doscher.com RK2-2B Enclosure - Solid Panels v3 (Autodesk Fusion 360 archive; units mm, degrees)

design "Recovery Kit v2 and v2b Frame - Solid Panels" references "6886K111_Flush-Mount 16 mm Panel-Mount Push-Button Switch", "1422N13_Panel-Mount Data Adapter", "6168T59_Push-In Signal Power Connectors(1)"
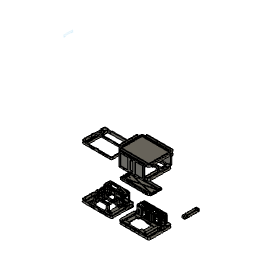
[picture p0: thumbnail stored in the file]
parameter "d2034" = 15
parameter "d2035" = 2.8
parameter "d1378" = 9.5
parameter "d1379" = 10
parameter "d1380" = 9.5
parameter "d1381" = 10
parameter "d1382" = 9.5
parameter "d1383" = 10
parameter "d1384" = 9.5
parameter "d1385" = 10
parameter "d1386" = 2.8
parameter "d1387" = 2.8
parameter "d1388" = 2.8
parameter "d1389" = 2.8
parameter "d1390" = 2.8
parameter "d1391" = 2.8
parameter "d1392" = -2000
parameter "d1393" = 0
parameter "d1394" = -3.5
parameter "d1395" = 6
parameter "d1396" = -3.5
parameter "d1397" = 6
parameter "d1398" = -3.5
parameter "d1399" = 6
parameter "d1400" = -3.5
parameter "d1401" = 6
parameter "d1402" = -3.5
parameter "d1403" = 6
parameter "d1404" = -3.5
parameter "d1405" = 6
parameter "d1406" = -3.5
parameter "d1407" = 6
parameter "d1408" = -3.5
parameter "d1409" = 6
parameter "d1410" = 2.8
parameter "d1411" = 2.8
parameter "d1412" = 2.8
parameter "d1413" = 2.8
parameter "d1414" = -1000
parameter "d1415" = 0
parameter "d1416" = 2.8
parameter "d1417" = 2.8
parameter "d1418" = -1000
parameter "d1419" = 0
parameter "d1420" = -3.5
parameter "d1421" = 6
parameter "d1422" = -3.5
parameter "d1423" = 6
parameter "d1424" = -3.5
parameter "d1425" = 6
parameter "d1426" = -3.5
parameter "d1427" = 6
parameter "d1428" = -3.5
parameter "d1429" = 6
parameter "d1430" = -3.5
parameter "d1431" = 6
parameter "d1432" = 8
parameter "d1433" = 4
parameter "d1434" = 8
parameter "d1435" = 10
parameter "d1436" = -3.5
parameter "d1437" = 0
parameter "d1438" = 8
parameter "d1439" = 8
parameter "d1440" = 8
parameter "d1441" = 8
parameter "d1442" = 10
parameter "d1443" = -3.5
parameter "d1444" = 0
parameter "d1446" = 2
parameter "d1447" = -5
parameter "d1448" = 0
parameter "d1450" = 2
parameter "d1451" = 5
parameter "d1452" = -5
parameter "d1453" = -10
parameter "d1454" = 0
parameter "d1455" = -5
parameter "d1456" = 0
parameter "d1458" = 2
parameter "d1460" = 2
parameter "d1462" = 2
parameter "d1463" = 5
parameter "d1464" = -5
parameter "d1465" = -10
parameter "d1466" = 0
parameter "d1468" = 2
parameter "d1469" = -5
parameter "d1470" = 0
parameter "d1472" = 2
parameter "d1473" = 10
parameter "d1474" = 12
parameter "d1475" = 10
parameter "d1476" = 12
parameter "d1477" = 10
parameter "d1478" = 12
parameter "d1479" = 10
parameter "d1480" = 12
parameter "d1481" = 2.8
parameter "d1482" = 2.8
parameter "d1483" = 2.8
parameter "d1484" = 2.8
parameter "d1485" = -100
parameter "d1486" = 0
parameter "d1487" = -2
parameter "d1488" = 0
parameter "d1489" = 3
parameter "d1490" = 2.8
parameter "d1491" = 2.8
parameter "d1492" = 2.8
parameter "d1493" = 2.8
parameter "d1494" = -40
parameter "d1495" = 0
parameter "d1496" = -410
parameter "d1497" = 0
parameter "d1498" = -3.5
parameter "d1499" = 6
parameter "d1502" = 6
parameter "d1503" = 6
parameter "d1504" = 6
parameter "d1505" = 6
parameter "d1506" = 6
parameter "d1507" = 8
parameter "d1508" = 8
parameter "d1509" = 8
parameter "d1510" = 8
parameter "d1511" = 8
parameter "d1512" = 8
parameter "d1513" = 8
parameter "d1514" = 8
parameter "d1515" = 8
parameter "d1516" = 8
parameter "d1517" = 8
parameter "d1518" = 8
parameter "d1519" = 8
parameter "d1520" = 8
parameter "d1521" = 8
parameter "d1522" = 8
parameter "d1523" = 8
parameter "d1524" = 8
parameter "d1525" = 8
parameter "d1526" = 8
parameter "d1527" = -3.5
parameter "d1528" = 0
parameter "d1529" = 0.4
parameter "d1530" = -15
parameter "d1531" = 0
parameter "d1532" = -10
parameter "d1533" = 10
parameter "d1534" = 20
parameter "d1535" = 10
parameter "d1536" = 20
parameter "d1537" = -15
parameter "d1538" = 0
parameter "d1539" = 10
parameter "d1540" = 15
parameter "d1541" = 10
parameter "d1542" = 15
parameter "d1543" = 2.8
parameter "d1544" = 2.8
parameter "d1545" = -20
parameter "d1546" = 0
parameter "d1547" = 10
parameter "d1548" = 15
parameter "d1549" = 10
parameter "d1550" = 15
parameter "d1551" = 2.8
parameter "d1552" = 2.8
parameter "d1553" = -20
parameter "d1554" = 0
parameter "d1555" = 3
parameter "d1556" = 30
parameter "d1557" = 0
parameter "d1558" = -30
parameter "d1559" = 0
parameter "d1560" = 30
parameter "d1561" = 0
parameter "d1562" = -30
parameter "d1563" = 0
parameter "d1565" = 3
parameter "d1566" = 3
parameter "d1567" = 5
parameter "d1568" = 0
parameter "d1569" = -2
parameter "d1570" = 2.8
parameter "d1571" = -2
parameter "d1572" = 2.8
parameter "d1573" = -3
parameter "d1574" = 6
parameter "d1575" = -3
parameter "d1576" = 6
parameter "d1577" = -50
parameter "d1578" = 2.8
parameter "d1579" = -50
parameter "d1580" = 2.8
parameter "d1581" = -50
parameter "d1582" = 2.8
parameter "d1583" = -75
parameter "d1584" = 2.8
parameter "d1585" = -70
parameter "d1586" = 2.8
parameter "d1587" = -100
parameter "d1588" = 2.8
parameter "d1589" = -100
parameter "d1590" = 2.8
parameter "d1591" = -100
parameter "d1592" = 2.8
parameter "d1593" = -100
parameter "d1594" = 2.8
parameter "d1595" = -2
parameter "d1596" = 2.8
parameter "d1597" = -2
parameter "d1598" = 2.8
parameter "d1599" = -2
parameter "d1600" = 2.8
parameter "d1601" = -2
parameter "d1602" = 2.8
parameter "d1603" = -2
parameter "d1604" = 2.8
parameter "d1605" = -2
parameter "d1606" = 2.8
parameter "d1607" = -2
parameter "d1608" = 2.8
parameter "d1609" = -2
parameter "d1610" = 2.8
parameter "d1611" = -2
parameter "d1612" = 2.8
parameter "d1613" = -2
parameter "d1614" = 2.8
parameter "d1619" = -20
parameter "d1620" = 2.8
parameter "d1621" = -15
parameter "d1622" = 0
parameter "d1623" = -15
parameter "d1624" = 2.8
parameter "d1625" = -15
parameter "d1626" = 2.8
parameter "d1627" = -15
parameter "d1628" = 2.8
parameter "d1629" = -15
parameter "d1630" = 2.8
parameter "d1631" = -15
parameter "d1632" = 2.8
parameter "d1633" = -15
parameter "d1634" = 2.8
parameter "d1637" = 20
parameter "d1638" = 20
parameter "d1639" = -3.5
parameter "d1640" = 0
parameter "d1641" = -1.5
parameter "d1642" = 0
parameter "d1643" = 10
parameter "d1644" = 0
parameter "d1646" = 2
parameter "d1647" = -35
parameter "d1648" = 0
parameter "d1649" = -40
parameter "d1650" = 0
parameter "d1651" = -5
parameter "d1652" = 0
parameter "d1653" = -35
parameter "d1654" = 0
parameter "d1655" = 5
parameter "d1656" = 0
parameter "d1657" = -35
parameter "d1658" = 0
parameter "d1659" = 5
parameter "d1660" = 0
parameter "d1661" = -250
parameter "d1662" = 0
parameter "d1663" = -2
parameter "d1664" = 0
parameter "d1665" = -2
parameter "d1666" = 0
parameter "d1667" = 10
parameter "d1668" = -10
parameter "d1669" = -10
parameter "d1670" = 0
parameter "d1671" = 5
parameter "d1672" = -5
parameter "d1673" = 0
parameter "d1675" = 3
parameter "d1676" = 5
parameter "d1677" = 0
parameter "d1678" = 20
parameter "d1679" = 20
parameter "d1680" = 100
parameter "d1681" = 100
parameter "d1682" = 10
parameter "d1683" = 10
parameter "d1684" = -5
parameter "d1685" = 0
parameter "d1686" = -0.5
parameter "d1687" = 0
parameter "d1688" = -0.5
parameter "d1689" = 0
parameter "d1690" = -1
parameter "d1691" = 2.8
parameter "d1692" = -1
parameter "d1693" = 2.8
parameter "d1694" = -1
parameter "d1695" = 2.8
parameter "d1696" = -1
parameter "d1697" = 2.8
parameter "d1698" = -1
parameter "d1699" = 2.8
parameter "d1700" = -1
parameter "d1701" = 2.8
parameter "d1702" = -1
parameter "d1703" = 2.8
parameter "d1704" = -1
parameter "d1705" = 2.8
parameter "d1706" = 12.5
parameter "d1707" = 12.5
parameter "d1708" = 12.5
parameter "d1709" = 12.5
parameter "d1710" = -10
parameter "d1711" = 0
parameter "d1712" = 10
parameter "d1713" = 10
parameter "d1715" = 3
parameter "d1716" = -0.5
parameter "d1717" = 0
parameter "d1718" = -10
parameter "d1719" = 0
parameter "d1720" = 1
parameter "d1721" = -5
parameter "d1722" = 0
parameter "d1723" = 42
parameter "d1724" = 70
parameter "d1725" = 42
parameter "d1726" = 70
parameter "d1727" = 170
parameter "d1728" = 42
parameter "d1729" = 170
parameter "d1730" = 42
parameter "d1731" = 14
parameter "d1732" = 14
parameter "d1733" = 14
parameter "d1734" = 14
parameter "d1735" = 14
parameter "d1736" = 14
parameter "d1737" = 14
parameter "d1738" = 14
parameter "d1739" = -5
parameter "d1740" = 0
parameter "d1741" = 11
parameter "d1742" = 7
parameter "d1743" = 7
parameter "d1744" = 7
parameter "d1745" = 7
parameter "d1746" = 7
parameter "d1747" = 7
parameter "d1748" = 7
parameter "d1749" = 7
parameter "d1750" = 7
parameter "d1751" = 7
parameter "d1752" = 7
parameter "d1753" = 7
parameter "d1754" = 7
parameter "d1755" = 7
parameter "d1756" = 7
parameter "d1757" = 7
parameter "d1758" = 2.8
parameter "d1759" = 2.8
parameter "d1760" = 2.8
parameter "d1761" = 2.8
parameter "d1762" = 2.8
parameter "d1763" = 2.8
parameter "d1764" = 2.8
parameter "d1765" = 2.8
parameter "d1766" = -70
parameter "d1767" = 0
parameter "d1768" = -320
parameter "d1769" = 0
parameter "d1770" = -7
parameter "d1771" = -12
parameter "d1772" = 5
parameter "d1773" = -5
parameter "d1774" = 5
parameter "d1775" = -5
parameter "d1776" = 7
parameter "d1777" = 0
parameter "d1779" = 2
parameter "d1780" = 5
parameter "d1781" = 5
parameter "d1782" = 5
parameter "d1783" = 5
parameter "d1784" = -10
parameter "d1785" = 0
parameter "d1786" = -5
parameter "d1787" = 0
parameter "d1788" = -4
parameter "d1789" = 0
parameter "d1790" = 2
parameter "d1791" = 0
parameter "d1792" = -3
parameter "d1793" = -3
parameter "d1794" = -3
parameter "d1795" = -3
parameter "d1796" = 3
parameter "d1797" = 0
parameter "d1798" = 6
parameter "d1799" = 6
parameter "d1800" = 6
parameter "d1801" = 6
parameter "d1802" = 6
parameter "d1803" = 6
parameter "d1804" = 6
parameter "d1805" = 6
parameter "d1806" = 6
parameter "d1807" = 6
parameter "d1808" = 6
parameter "d1809" = 6
parameter "d1810" = 6
parameter "d1811" = 6
parameter "d1812" = 6
parameter "d1813" = 6
parameter "d1814" = 6
parameter "d1815" = 6
parameter "d1816" = 6
parameter "d1817" = 6
parameter "d1818" = 6
parameter "d1819" = 6
parameter "d1820" = 6
parameter "d1821" = 6
parameter "d1822" = -3.5
parameter "d1823" = 0
parameter "d1825" = 3
parameter "d1826" = 7
parameter "d1827" = 20
parameter "d1828" = 7
parameter "d1829" = -10
parameter "d1830" = 0
parameter "d1831" = 2
parameter "d1832" = -2
parameter "d1833" = 0
parameter "d1834" = -10
parameter "d1835" = 0
parameter "d1836" = 4
parameter "d1837" = 4
parameter "d1838" = 4
parameter "d1839" = -10
parameter "d1840" = 0
parameter "d1841" = -4
parameter "d1842" = 0
parameter "d1843" = -4
parameter "d1844" = 0
parameter "d1845" = 3.5
parameter "d1847" = 7
parameter "d1848" = -2
parameter "d1849" = 0
parameter "d1850" = 4
parameter "d1851" = 0
parameter "d1852" = 3.5
parameter "d1853" = -60
parameter "d1854" = 0
parameter "d1855" = 47
parameter "d1856" = 0
parameter "d1857" = -16
parameter "d1858" = 0
parameter "d1859" = 7
parameter "d1861" = 3
parameter "d1862" = 1
parameter "d1863" = 0
parameter "d1864" = -1
parameter "d1865" = 0
parameter "d1866" = -1
parameter "d1867" = 0
parameter "d1868" = -20
parameter "d1869" = 0
parameter "d1870" = -30
parameter "d1871" = 0
parameter "d1872" = -30
parameter "d1873" = 0
parameter "d1875" = 2
parameter "d1878" = 5.25
parameter "d1879" = 4
parameter "d1880" = 4
parameter "d1881" = 0
parameter "d1882" = 12
parameter "d1883" = 12
parameter "d1884" = 12
parameter "d1885" = 12
parameter "d1886" = -5
parameter "d1887" = 0
parameter "d1888" = 5
parameter "d1890" = 2
parameter "d1891" = 12
parameter "d1892" = 12
parameter "d1893" = 12
parameter "d1894" = 12
parameter "d1895" = -5
parameter "d1896" = 0
parameter "d1897" = 5
parameter "d1899" = 2
parameter "d1900" = 8
parameter "d1901" = 0
parameter "d1902" = -0.5
parameter "d1903" = 0
parameter "d1904" = -0.5
parameter "d1905" = 0
parameter "d1906" = 20
parameter "d1907" = 0
parameter "d1908" = 5
parameter "d1909" = -10
parameter "d1910" = 0
parameter "d1912" = 4
parameter "d1914" = -3.5
parameter "d1915" = 6.5
parameter "d1917" = -3.5
parameter "d1918" = 6.5
parameter "d1919" = 3
parameter "d1921" = 2
parameter "d1922" = 3
parameter "d1923" = 3
parameter "d1924" = -3
parameter "d1925" = -20
parameter "d1926" = 0
parameter "d1927" = -20
parameter "d1928" = 0
parameter "d1929" = 5
parameter "d1930" = 15
parameter "d1931" = 5
parameter "d1932" = 15
parameter "d1933" = -20
parameter "d1934" = 0
parameter "d1935" = 14
parameter "d1936" = 0
parameter "d1937" = 5
parameter "d1938" = 0
parameter "d1939" = 5
parameter "d1940" = 0
parameter "d1941" = -4
parameter "d1942" = 0
parameter "d1943" = -0.5
parameter "d1944" = 0
parameter "d1945" = -56
parameter "d1946" = 0
parameter "d1947" = -0.5
parameter "d1948" = 0
parameter "d1949" = 5
parameter "d1950" = 0
parameter "d1951" = 2
parameter "d1952" = 0
parameter "d1953" = 24
parameter "d1954" = 7
parameter "d1955" = 0
parameter "d1957" = 4
parameter "d1958" = 1
parameter "d1959" = 0
parameter "d1960" = -0.3
parameter "d1961" = 0
parameter "d1962" = -30
parameter "d1963" = 0
parameter "d1964" = 6.5
parameter "d1965" = 6.5
parameter "d1966" = 6.5
parameter "d1967" = 21
parameter "d1968" = 6.5
parameter "d1969" = 21
parameter "d1970" = 6.5
parameter "d1971" = 21
parameter "d1972" = 6.5
parameter "d1973" = 21
parameter "d1974" = 6.5
parameter "d1975" = 21
parameter "d1976" = 6.5
parameter "d1977" = 21
parameter "d1978" = 6.5
parameter "d1979" = 21
parameter "d1980" = 6.5
parameter "d1981" = 21
parameter "d1982" = 6.5
parameter "d1983" = -9.5
parameter "d1984" = 0
parameter "d1986" = 2
parameter "d1988" = 2
parameter "d1990" = 2
parameter "d1992" = 2
parameter "d1994" = 2
parameter "d1995" = -3
parameter "d1996" = 3
parameter "d1997" = -3
parameter "d1998" = 0
parameter "d1999" = 3
parameter "d2000" = -10
parameter "d2001" = 0
parameter "d2002" = 3
parameter "d2003" = 0
parameter "d2005" = 3
parameter "d2006" = -14
parameter "d2007" = 0
parameter "d2008" = 1
parameter "d2009" = 0
parameter "d2010" = -1
parameter "d2011" = 0
parameter "d2012" = 2
parameter "d2013" = 0
parameter "d2014" = -2
parameter "d2015" = 0
parameter "d2016" = 2.5
parameter "d2017" = 0
parameter "d2018" = 2
parameter "d2019" = 0
parameter "d2020" = -4.5
parameter "d2021" = 0
parameter "d2022" = -6.5
parameter "d2023" = 0
parameter "d2024" = -6.5
parameter "d2025" = 0
parameter "d2026" = -6.5
parameter "d2027" = 0
parameter "d639" = 5
parameter "d640" = 0
parameter "d641" = 5
parameter "d642" = 5
parameter "d643" = -50
parameter "d644" = 11.1
parameter "d645" = -2
parameter "d646" = 10
parameter "d647" = 0
parameter "d648" = -1.5
parameter "d649" = 0
parameter "d650" = 3
parameter "d651" = -20
parameter "d652" = 5
parameter "d653" = -10
parameter "d654" = 5
parameter "d655" = 29
parameter "d656" = 10
parameter "d657" = -5
parameter "d658" = 0
parameter "d659" = 1
parameter "d660" = 2
parameter "d661" = 3
parameter "d662" = 3
parameter "d663" = 5
parameter "d664" = 0
parameter "d665" = 5
parameter "d666" = 5
parameter "d667" = 0
parameter "d668" = 5
parameter "d669" = 5
parameter "d670" = 0
parameter "d671" = 5
parameter "d672" = 5
parameter "d673" = 0
parameter "d674" = 3
parameter "d675" = 3
parameter "d676" = 3
parameter "d678" = 0.1
parameter "d679" = -60
parameter "d680" = 0
parameter "d681" = 2
parameter "d682" = 1
parameter "d683" = 5
parameter "d684" = 0
parameter "d685" = 5
parameter "d686" = 1
parameter "d687" = -4
parameter "d688" = 2.8
parameter "d689" = -4
parameter "d690" = 2.8
parameter "d691" = -4
parameter "d692" = 2.8
parameter "d693" = -4
parameter "d694" = 2.8
parameter "d695" = 5
parameter "d696" = 0
parameter "d697" = 5
parameter "d698" = 0
parameter "d699" = 5
parameter "d700" = 5
parameter "d701" = -3
parameter "d702" = 2.8
parameter "d703" = -3
parameter "d704" = 2.8
parameter "d705" = -3
parameter "d706" = 2.8
parameter "d707" = -3
parameter "d708" = 2.8
parameter "d709" = -2
parameter "d710" = 0
parameter "d711" = -2
parameter "d712" = 0
parameter "d713" = -2
parameter "d714" = 0
parameter "d715" = -2
parameter "d716" = 0
parameter "d717" = 225
parameter "d718" = 74
parameter "d719" = 36.5
parameter "d720" = 36.5
parameter "d721" = 17.9
parameter "d722" = 17.9
parameter "d723" = 56
parameter "d724" = 56
parameter "d725" = 17.5
parameter "d726" = 17.5
parameter "d727" = 56
parameter "d728" = 56
parameter "d729" = 17.5
parameter "d730" = 17.5
parameter "d731" = 1.8
parameter "d732" = 1.8
parameter "d733" = 1.8
parameter "d734" = 1.8
parameter "d735" = 1.8
parameter "d736" = 1.8
parameter "d737" = -5
parameter "d738" = 7
parameter "d739" = 7
parameter "d740" = 7
parameter "d741" = 7
parameter "d742" = 7
parameter "d743" = 7
parameter "d744" = 5
parameter "d745" = 0
parameter "d746" = -4
parameter "d747" = 3
parameter "d748" = 0
parameter "d749" = 2
parameter "d750" = 7
parameter "d751" = 2
parameter "d752" = 7
parameter "d753" = 2
parameter "d754" = 7
parameter "d755" = 2
parameter "d756" = 7
parameter "d757" = 2
parameter "d758" = 7
parameter "d759" = 2
parameter "d760" = 7
parameter "d761" = -50
parameter "d762" = 1.8
parameter "d763" = -50
parameter "d764" = 1.8
parameter "d765" = -50
parameter "d766" = 1.8
parameter "d767" = -80
parameter "d768" = 1.8
parameter "d769" = -50
parameter "d770" = 1.8
parameter "d771" = -50
parameter "d772" = 1.8
parameter "d773" = 1
parameter "d774" = -3
parameter "d775" = 0
parameter "d776" = 5
parameter "d777" = 0
parameter "d778" = 2
parameter "d779" = 115
parameter "d780" = 20
parameter "d781" = 2
parameter "d782" = 0
parameter "d783" = 10
parameter "d784" = 20
parameter "d785" = 0
parameter "d786" = 10
parameter "d787" = 0
parameter "d788" = -10
parameter "d789" = 0
parameter "d790" = 15
parameter "d791" = -12
parameter "d792" = 0
parameter "d794" = 2
parameter "d796" = 5
parameter "d797" = -5
parameter "d798" = 5
parameter "d799" = -27
parameter "d800" = 0
parameter "d802" = 0.1
parameter "d803" = 110
parameter "d804" = 0
parameter "d805" = 0
parameter "d806" = -1
parameter "d807" = 2
parameter "d808" = 5
parameter "d809" = 0
parameter "d810" = -15
parameter "d811" = 0
parameter "d812" = 3
parameter "d813" = 1
parameter "d814" = -3
parameter "d815" = 0
parameter "d816" = -3
parameter "d817" = -50
parameter "d818" = 0
parameter "d820" = 0.1
parameter "d821" = -0.1
parameter "d822" = -0.1
parameter "d823" = 3
parameter "d824" = -0.5
parameter "d825" = 0
parameter "d826" = -0.5
parameter "d827" = 0
parameter "d828" = 33
parameter "d829" = 10.5
parameter "d830" = 7.8
parameter "d831" = -7
parameter "d832" = 0
parameter "d833" = 3.4
parameter "d834" = -9
parameter "d835" = 0
parameter "d836" = 0.5
parameter "d837" = 0
parameter "d838" = 0.5
parameter "d839" = 0
parameter "d840" = -2
parameter "d841" = 0
parameter "d842" = 23.5
parameter "d843" = 2
parameter "d844" = -7.5
parameter "d845" = 0
parameter "d846" = -2
parameter "d847" = 0
parameter "d848" = -2
parameter "d849" = 0
parameter "d850" = 23.5
parameter "d851" = 2
parameter "d852" = -5
parameter "d853" = 0
parameter "d854" = 1.9
parameter "d855" = 0
parameter "d856" = 1.9
parameter "d857" = 0
parameter "d858" = 23.5
parameter "d859" = 2
parameter "d860" = -20
parameter "d861" = 0
parameter "d862" = -2
parameter "d863" = 0
parameter "d864" = 23.5
parameter "d865" = 2
parameter "d866" = -10
parameter "d867" = 0
parameter "d868" = -2
parameter "d869" = 0
parameter "d870" = 5
parameter "d871" = 5
parameter "d872" = 5
parameter "d873" = 5
parameter "d874" = 2
parameter "d875" = 0
parameter "d876" = 7
parameter "d877" = 0
parameter "d878" = 7
parameter "d879" = 7
parameter "d880" = 7
parameter "d881" = 7
parameter "d882" = -7
parameter "d883" = 0
parameter "d884" = -15
parameter "d885" = 0
parameter "d886" = 7
parameter "d887" = 7
parameter "d888" = 4
parameter "d889" = -10
parameter "d890" = 0
parameter "d891" = 7
parameter "d892" = 7
parameter "d893" = 2.3
parameter "d894" = -5
parameter "d895" = 0
parameter "d896" = 7
parameter "d897" = 7
parameter "d898" = 2.3
parameter "d899" = -5
parameter "d900" = 0
parameter "d901" = 7
parameter "d902" = 1.5
parameter "d903" = -2
parameter "d904" = 2
parameter "d905" = 0
parameter "d906" = 0
parameter "d907" = -2
parameter "d908" = 2
parameter "d909" = 2
parameter "d910" = -7
parameter "d911" = 0
parameter "d912" = -2
parameter "d913" = 0
parameter "d914" = -2
parameter "d915" = 0
parameter "d916" = 1.25
parameter "d917" = 0
parameter "d918" = 1.25
parameter "d919" = 0
parameter "d920" = -1
parameter "d921" = -1
parameter "d922" = 0
parameter "d923" = 0
parameter "d924" = -1
parameter "d925" = 0
parameter "d926" = 1
parameter "d927" = 0
parameter "d928" = 0
parameter "d929" = -10
parameter "d930" = 0
parameter "d931" = -50
parameter "d932" = 2.1
parameter "d933" = -50
parameter "d934" = 2.1
parameter "d935" = -50
parameter "d936" = 2.1
parameter "d937" = -50
parameter "d938" = 2.1
parameter "d939" = -50
parameter "d940" = 2.1
parameter "d941" = -50
parameter "d942" = 2.1
parameter "d943" = 1
parameter "d944" = 0
parameter "d945" = 600
parameter "d946" = 0
parameter "d947" = -145
parameter "d948" = 1
parameter "d949" = 0.1
parameter "d950" = -1.5
parameter "d951" = 0
parameter "d952" = -96
parameter "d953" = 1
parameter "d954" = 40
parameter "d955" = 0
parameter "d956" = 0.1
parameter "d957" = -1.5
parameter "d958" = 0
parameter "d959" = -200
parameter "d960" = 1
parameter "d961" = -0.3
parameter "d962" = -1
parameter "d963" = 0
parameter "d964" = -100
parameter "d965" = 1
parameter "d966" = -500
parameter "d967" = 1
parameter "d968" = -500
parameter "d969" = 1
parameter "d970" = 0
parameter "d971" = 0
parameter "d972" = 50
parameter "d973" = -0.1
parameter "d974" = -1.5
parameter "d975" = 0
parameter "d976" = -0.1
parameter "d977" = -1.5
parameter "d978" = 0
parameter "d979" = 1.2
parameter "d980" = 0
parameter "d981" = 0
parameter "d982" = 0.1
parameter "d983" = -1
parameter "d984" = 0
parameter "d985" = 0
parameter "d986" = 0
parameter "d987" = 65
parameter "d988" = -1.5
parameter "d989" = 2
parameter "d990" = 0
parameter "d991" = -1.5
parameter "d992" = 2
parameter "d993" = 0
parameter "d994" = 1
parameter "d995" = 0
parameter "d996" = 0
parameter "d997" = 1
parameter "d998" = 0
parameter "d999" = 0
parameter "d1000" = -10
parameter "d1001" = 2.2
parameter "d1002" = -10
parameter "d1003" = 2.2
parameter "d1004" = -10
parameter "d1005" = 2.2
parameter "d1006" = -10
parameter "d1007" = 2.2
parameter "d1008" = -10
parameter "d1009" = 2.2
parameter "d1010" = -10
parameter "d1011" = 2.2
parameter "d1012" = 5
parameter "d1013" = 5
parameter "d1014" = 5
parameter "d1015" = 5
parameter "d1016" = 5
parameter "d1017" = 5
parameter "d1018" = 2
parameter "d1019" = 0
parameter "d1020" = 1.5
parameter "d1021" = 0
parameter "d1022" = -9
parameter "d1023" = 0
parameter "d1024" = 11
parameter "d1025" = 2
parameter "d1026" = 8
parameter "d1027" = 0
parameter "d1028" = 2
parameter "d1029" = 0
parameter "d1030" = -2
parameter "d1031" = 1
parameter "d1032" = 0
parameter "d1033" = 8
parameter "d1034" = 0
parameter "d1035" = 17
parameter "d1036" = 8
parameter "d1037" = 0
parameter "d1038" = 8
parameter "d1039" = 8
parameter "d1040" = 8
parameter "d1041" = 8
parameter "d1042" = 8
parameter "d1043" = 3.8
parameter "d1044" = 3.8
parameter "d1045" = -5
parameter "d1046" = 0
parameter "d1047" = 2
parameter "d1048" = 2
parameter "d1049" = 2
parameter "d1050" = 0
parameter "d1051" = 2
parameter "d1052" = 15
parameter "d1053" = 4
parameter "d1054" = 15
parameter "d1055" = 5
parameter "d1056" = 4
parameter "d1057" = 15
parameter "d1058" = 4
parameter "d1059" = 15
parameter "d1060" = 4
parameter "d1061" = 5
parameter "d1062" = 5
parameter "d1063" = 15
parameter "d1064" = 4
parameter "d1065" = 5
parameter "d1066" = 5
parameter "d1067" = 4
parameter "d1068" = 5
parameter "d1069" = 4
parameter "d1070" = 5
parameter "d1071" = 4
parameter "d1072" = 5
parameter "d1073" = 4
parameter "d1074" = 5
parameter "d1075" = -30
parameter "d1076" = 0
parameter "d1077" = 2
parameter "d1078" = 1
parameter "d1079" = 1
parameter "d1080" = 8
parameter "d1081" = 8
parameter "d1082" = 8
parameter "d1083" = 8
parameter "d1084" = 3.8
parameter "d1085" = 3.8
parameter "d1086" = -5
parameter "d1087" = 0
parameter "d1088" = 5
parameter "d1089" = 0
parameter "d1090" = 19
parameter "d1091" = 11.5
parameter "d1092" = 3.8
parameter "d1093" = 3.8
parameter "d1094" = -5
parameter "d1095" = 0
parameter "d1096" = 2
parameter "d1097" = -50
parameter "d1098" = 2.5
parameter "d1099" = -50
parameter "d1100" = 2.5
parameter "d1101" = 2
parameter "d1102" = 10
parameter "d1103" = 2
parameter "d1104" = 10
parameter "d1105" = -110
parameter "d1106" = 0
parameter "d1107" = 2
parameter "d1108" = 2
parameter "d1109" = 2
parameter "d1110" = -1
parameter "d1111" = 0
parameter "d1112" = 106
parameter "d1113" = 0
parameter "d1114" = 14
parameter "d1115" = 14
parameter "d1116" = 14
parameter "d1117" = 14
parameter "d1118" = 14
parameter "d1119" = 14
parameter "d1120" = 14
parameter "d1121" = 14
parameter "d1126" = 4
parameter "d1127" = 4
parameter "d1128" = 2
parameter "d1129" = 0
parameter "d1131" = 3
parameter "d1133" = 3
parameter "d1134" = 8
parameter "d1135" = 8
parameter "d1136" = 28.5
parameter "d1137" = 2
parameter "d1138" = 0.3
parameter "d1139" = 0.3
parameter "d1140" = 12
parameter "d1141" = 12
parameter "d1142" = 5
parameter "d1143" = 0
parameter "d1144" = 0
parameter "d1145" = 0
parameter "d1146" = 13
parameter "d1147" = 3
parameter "d1148" = 0
parameter "d1149" = 6.5
parameter "d1150" = 0
parameter "d1151" = -0.336
parameter "d1152" = 0
parameter "d1153" = -0.305
parameter "d1154" = 0
parameter "d1155" = 1
parameter "d1156" = -6
parameter "d1157" = 0
parameter "d1158" = 0
parameter "d1159" = -16
parameter "d1160" = 0
parameter "d1161" = 2
parameter "d1162" = 0
parameter "d1163" = 3
parameter "d1164" = 0
parameter "d1165" = 23
parameter "d1166" = 4
parameter "d1167" = 24
parameter "d1168" = 4
parameter "d1169" = 22
parameter "d1170" = 4
parameter "d1171" = 25
parameter "d1172" = 4
parameter "d1173" = 0
parameter "d1174" = 16
parameter "d1175" = 0
parameter "d1176" = -1
parameter "d1177" = 0
parameter "d1178" = -2
parameter "d1179" = 0
parameter "d1180" = 2
parameter "d1181" = -3
parameter "d1182" = 0
parameter "d1183" = 24
parameter "d1184" = 0
parameter "d1185" = 13
parameter "d1186" = 1
parameter "d1187" = 2
parameter "d1188" = 0
parameter "d1189" = 2
parameter "d1190" = 7.8
parameter "d1191" = -6
parameter "d1192" = 3.1
parameter "d1193" = -34
parameter "d1194" = 0
parameter "d1195" = -25
parameter "d1196" = 0
parameter "d1197" = -20
parameter "d1198" = 0
parameter "d1199" = -14
parameter "d1200" = 0
parameter "d1201" = -16
parameter "d1202" = 0
parameter "d1203" = -1
parameter "d1204" = 0
parameter "d1205" = -1
parameter "d1206" = 0
parameter "d1207" = -1
parameter "d1208" = 0
parameter "d1209" = -3
parameter "d1210" = -1
parameter "d1211" = 0
base_feature "Base Feature" bodies "doscher.com RK2B display bracket left", "doscher.com RK2B battery grid rear", "doscher.com RK2B battery grid long outer", "doscher.com RK2B battery grid center", "doscher.com RK2B battery grid short outer", "doscher.com RK2B battery grid front", "doscher.com RK2B battery pillar lower left", "doscher.com RK2B battery pillar lower right"
component_insert "Component Insert1"
component_insert "Component Insert2"
component_insert "Component Insert3"
component_insert "Component Insert4"
component_insert "Component Insert5"
component_insert "Component Insert6"
component_insert "Component Insert7"
component_insert "Component Insert8"
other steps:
step "Extrude" AlongDistance -9 TaperAngle 0
step "CylinderPrimitive5" Height 15 Diameter 2.8
step "CylinderPrimitive6" Height 15 Diameter 2.8
step "Base Feature" bodies "Panel - Bottom x2 (Solid) (1)"
step "Move2"
step "Align3"
step "Move3"
step "Align4"
step "CylinderPrimitive7" Height 15 Diameter 2.8
step "Mirror" mirrorStitchTolerance 0.1
step "Align5"
step "CylinderPrimitive8" Height 15 Diameter 2.8
step "CylinderPrimitive9" Height 15 Diameter 2.8
step "Align6"
step "DeleteFace2"
step "Split6"
step "Move9"
step "Move10"
step "DeleteFace3"
step "DeleteFace4"
step "Move11"
step "Move12"
step "Mirror5" mirrorStitchTolerance 0.1
step "Move13"
step "Mirror6" mirrorStitchTolerance 0.1
step "Move14"
step "Mirror7" mirrorStitchTolerance 0.1
step "Move15"
step "Move16"
step "Move17"
step "Move18"
step "Move19"
step "Move20"
step "Move21"
step "DeleteFace5"
step "DeleteFace6"
step "DeleteFace7"
step "Move22"
step "Move23"
step "DeleteFace8"
step "DeleteFace9"
step "DeleteFace10"
step "DeleteFace11"
step "DeleteFace12"
step "DeleteFace13"
step "DeleteFace14"
step "DeleteFace15"
step "DeleteFace16"
step "DeleteFace17"
step "Move24"
step "Move25"
step "Move26"
step "Move27"
step "Move28"
step "Move29"
step "Move30"
step "DeleteFace18"
step "DeleteFace19"
step "DeleteFace20"
step "DeleteFace21"
step "Move31"
step "Move32"
step "DeleteFace22"
step "DeleteFace23"
step "DeleteFace24"
step "Move33"
step "DeleteFace25"
step "DeleteFace26"
step "DeleteFace27"
step "DeleteFace28"
step "DeleteFace29"
step "DeleteFace30"
step "DeleteFace31"
step "DeleteFace32"
step "DeleteFace33"
step "DeleteFace34"
step "DeleteFace35"
step "Move34"
step "Move35"
step "DeleteFace36"
step "DeleteFace37"
step "DeleteFace38"
step "MoveFace"
step "Move36"
step "Move37"
step "DeleteFace39"
step "DeleteFace40"
step "Move38"
step "Mirror8" mirrorStitchTolerance 0.1
step "Move39"
step "Move40"
step "Split7"
step "Move41"
step "Move42"
step "Move43"
step "Move44"
step "DeleteFace41"
step "DeleteFace42"
step "DeleteFace43"
step "DeleteFace44"
step "DeleteFace45"
step "DeleteFace46"
step "DeleteFace47"
step "DeleteFace48"
step "DeleteFace49"
step "DeleteFace50"
step "DeleteFace51"
step "DeleteFace52"
step "DeleteFace53"
step "DeleteFace54"
step "Move45"
step "Move46"
step "DeleteFace55"
step "DeleteFace56"
step "DeleteFace57"
step "DeleteFace58"
step "DeleteFace59"
step "DeleteFace60"
step "DeleteFace61"
step "DeleteFace62"
step "DeleteFace63"
step "DeleteFace64"
step "DeleteFace65"
step "DeleteFace66"
step "DeleteFace67"
step "DeleteFace68"
step "DeleteFace69"
step "DeleteFace70"
step "DeleteFace71"
step "DeleteFace72"
step "DeleteFace73"
step "DeleteFace74"
step "DeleteFace75"
step "DeleteFace76"
step "DeleteFace77"
step "DeleteFace78"
step "DeleteFace79"
step "DeleteFace80"
step "Move47"
step "Move48"
step "Sketch"
step "CopyPasteBodies"
named bodies: "doscher.com RK2B display bracket left", "doscher.com RK2B battery grid rear", "doscher.com RK2B battery grid long outer", "doscher.com RK2B battery grid center", "doscher.com RK2B battery grid short outer", "doscher.com RK2B battery grid front", "doscher.com RK2B battery pillar lower left", "doscher.com RK2B battery pillar lower right", "doscher.com RK2B battery pillar top left", "doscher.com RK2B battery pillar top center", "doscher.com RK2B battery pillar top right", "doscher.com RK2B display bracket right", "doscher.com RK2B primary frame", "doscher.com RK2B cartridge cavity back", "doscher.com RK2 primary frame", "doscher.com RK2 display frame v5", "doscher.com RK2 display bracket right", "doscher.com RK2 display bracket left", "doscher.com RK2 battery short end", "doscher.com RK2 battery middle", "doscher.com RK2 battery long end", "doscher.com RK2 battery rear", "doscher.com RK2 battery front", "doscher.com RK2 battery clip left", "doscher.com RK2 battery clip right", "doscher.com RK2 PCB tray adapter", "doscher.com RK2 and RK2B keyboard shim A", "doscher.com RK2 and RK2B keyboard shim B", "doscher.com RK2 and RK2B keyboard enclosure", "doscher.com RK2 and RK2B keyboard enclosure bracket", "doscher.com RK2B battery retainer loop", "doscher.com RK2B flat display frame", "Panel - Top (Solid)", "doscher.com RK2B primary frame (w/ mounting holes)", "Front and Rear Frame x4", "Interior Rear (Solid)", "Panel - Side (Solid)", "doscher.com RK2 primary frame (w/ mounting holes)", "Panel - Bottom x2 (Solid) (1)", "Panel - Bottom (Solid)"

design "6168T59_Push-In Signal Power Connectors(1)"
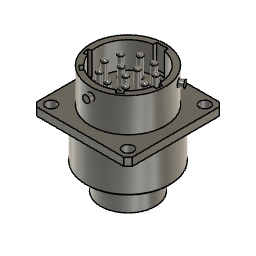
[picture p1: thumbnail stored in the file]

design "1422N13_Panel-Mount Data Adapter"
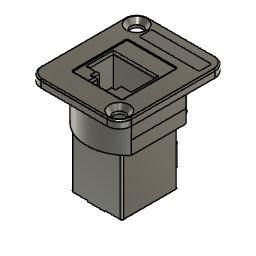
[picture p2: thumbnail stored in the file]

design "6886K111_Flush-Mount 16 mm Panel-Mount Push-Button Switch"
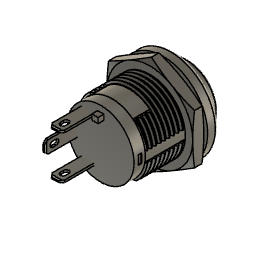
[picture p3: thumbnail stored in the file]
